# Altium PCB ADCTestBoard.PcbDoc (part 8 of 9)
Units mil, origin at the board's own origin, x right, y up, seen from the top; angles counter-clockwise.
Board outline 11022.62 x 9187 mil, 8 copper layers (TopLayer, InternalPlane1, InternalPlane2, InternalPlane3, InternalPlane4, InternalPlane5, MidLayer1, BottomLayer), stack 103.8 mil thick; 1282 components, 637 nets, 4473 pads, 1306 vias.
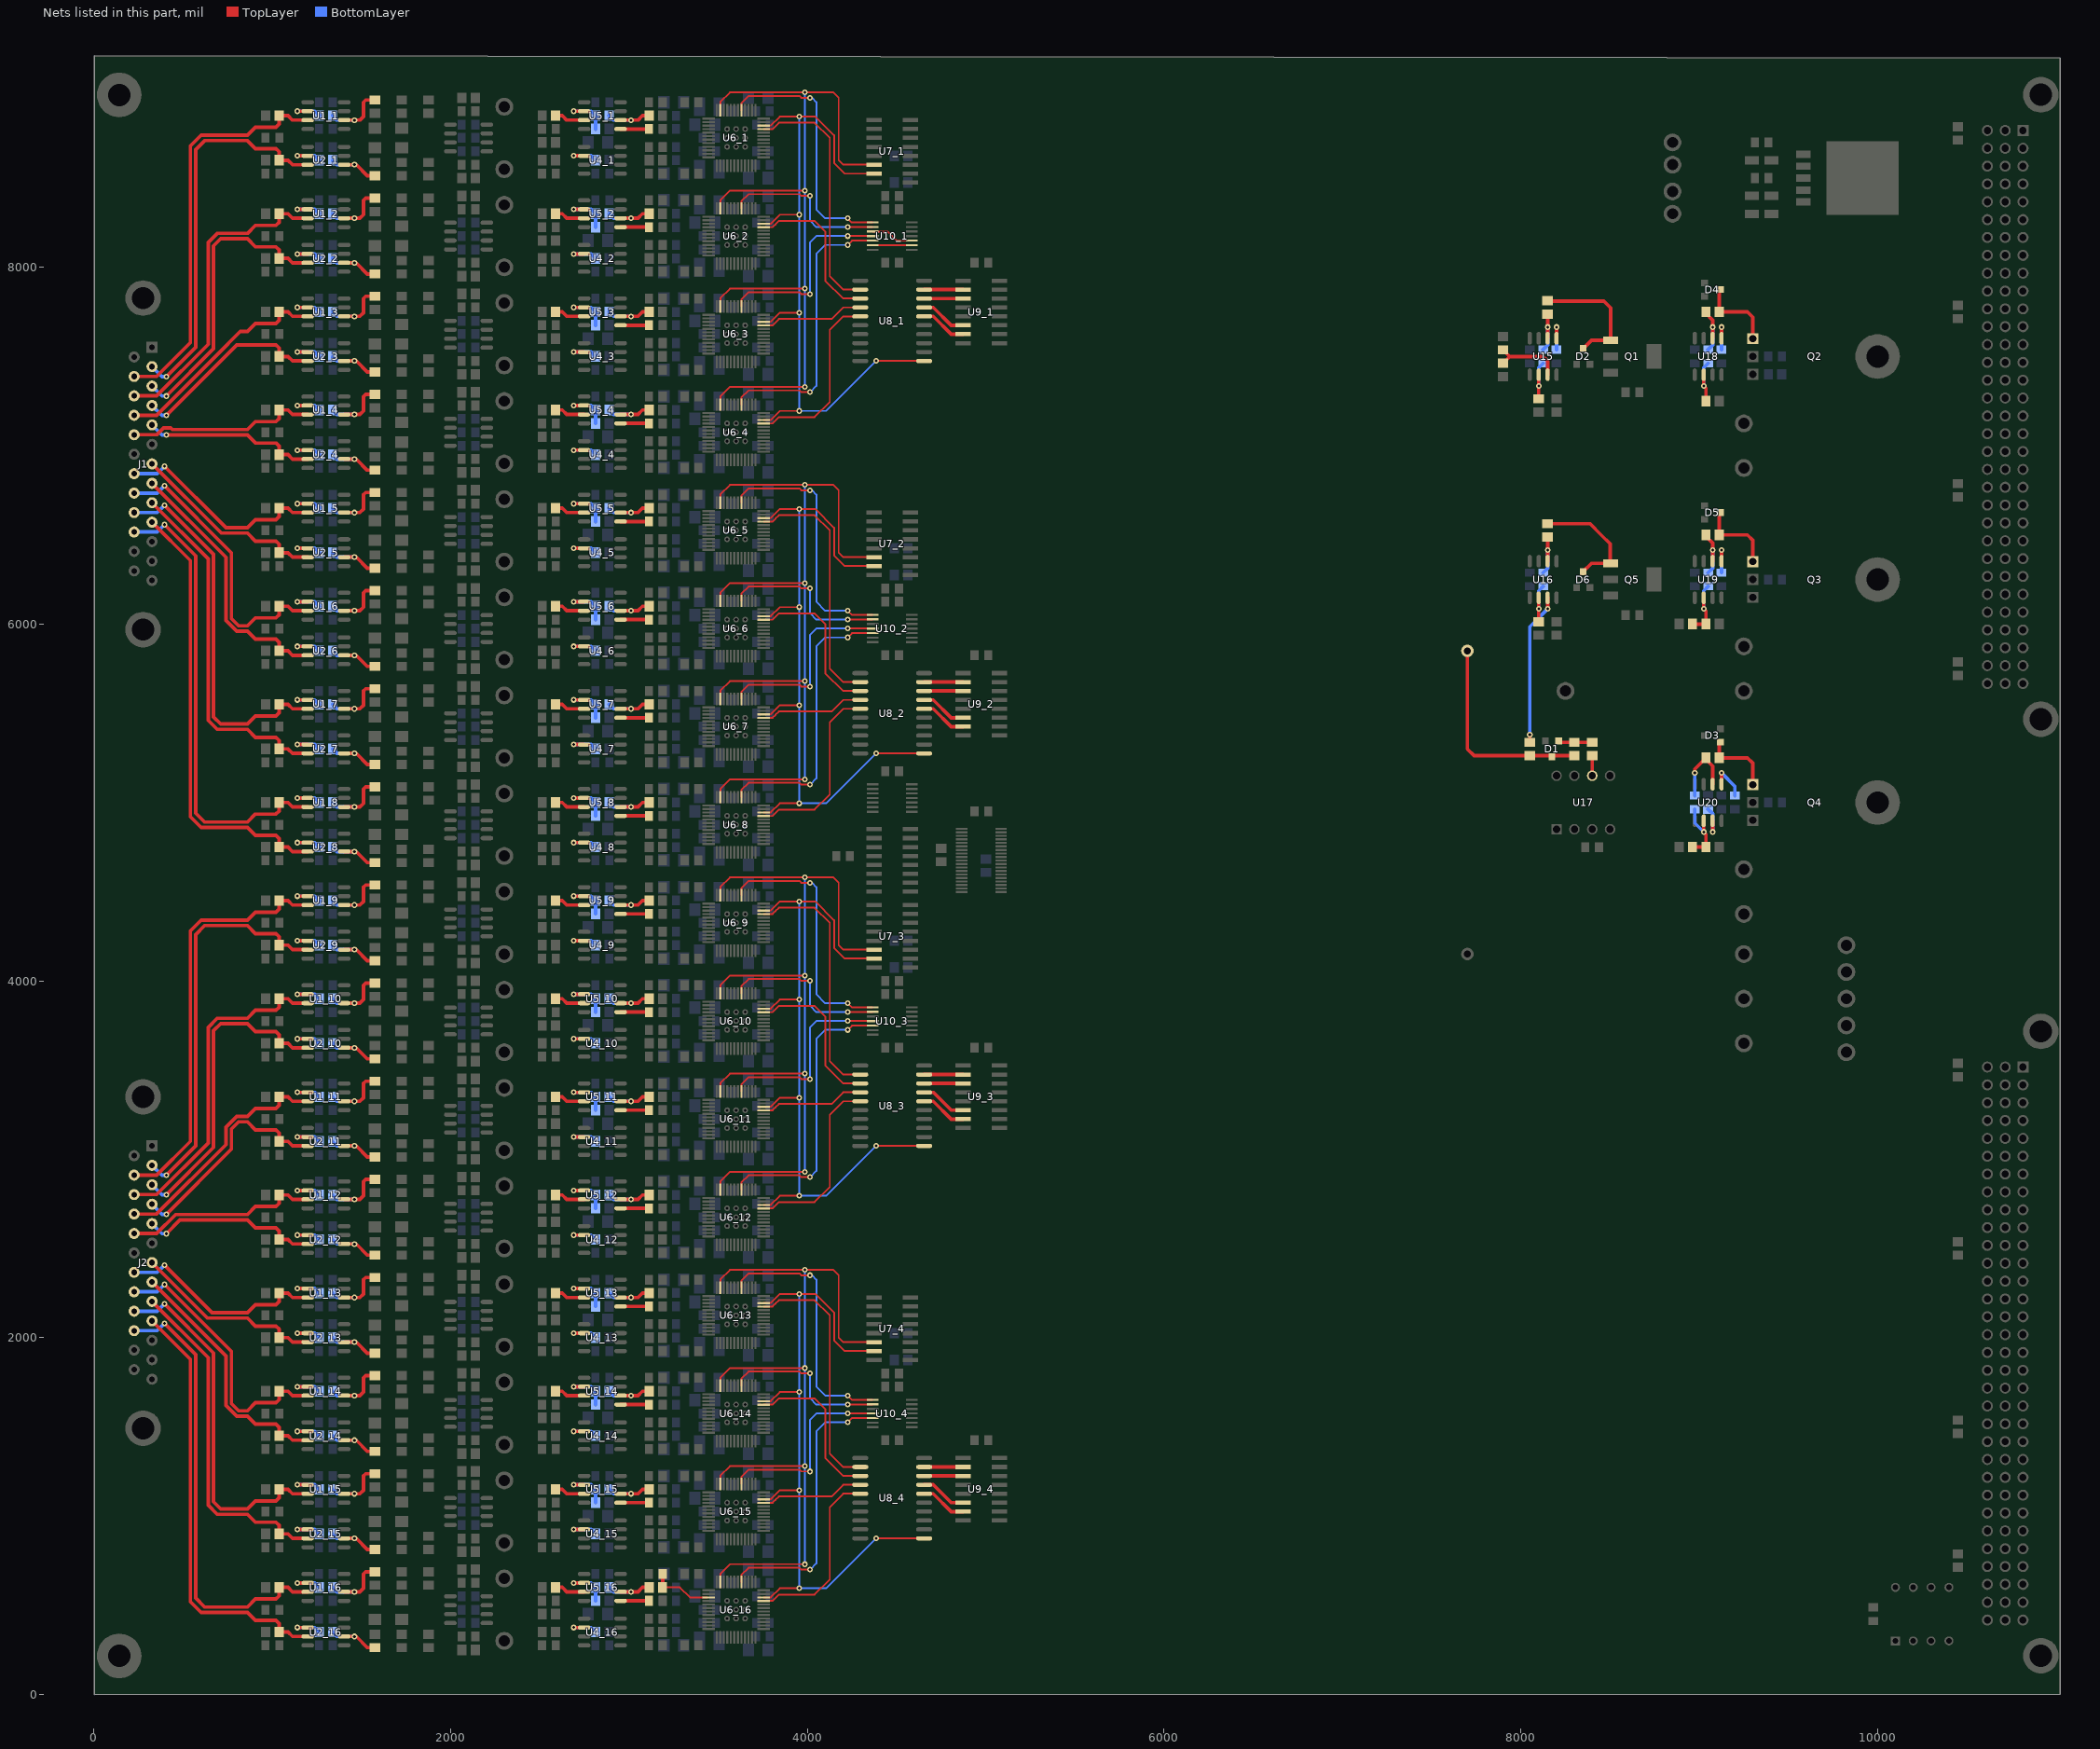
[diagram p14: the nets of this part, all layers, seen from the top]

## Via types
v1: diameter 32, hole 16, TopLayer to BottomLayer, 1306 vias

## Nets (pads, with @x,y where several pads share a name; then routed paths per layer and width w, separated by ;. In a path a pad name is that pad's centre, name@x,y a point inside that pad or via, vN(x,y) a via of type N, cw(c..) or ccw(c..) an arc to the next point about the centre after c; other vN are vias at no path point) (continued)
NetC36_16_1: C36_16.1 R19_16.1 U6_16.39 | length 346.9
  TopLayer w10: R19_16.1@3187.4,600 3285,600 3341.1,543.9 U6_16.39@3435.63,543.9
  TopLayer w20: R19_16.1@3187.4,600 3188.39,600.98 C36_16.1@3188.39,675
NetC37_1_1: C37_1.1 U5_1.5 | length 159.3
  TopLayer w20: U5_1.5@2952.36,8775 C37_1.1@3111.61,8775
NetC37_2_1: C37_2.1 U5_2.5 | length 159.3
  TopLayer w20: U5_2.5@2952.36,8225 C37_2.1@3111.61,8225
NetC37_3_1: C37_3.1 U5_3.5 | length 159.3
  TopLayer w20: U5_3.5@2952.36,7675 C37_3.1@3111.61,7675
NetC37_4_1: C37_4.1 U5_4.5 | length 159.3
  TopLayer w20: U5_4.5@2952.36,7125 C37_4.1@3111.61,7125
NetC37_5_1: C37_5.1 U5_5.5 | length 159.3
  TopLayer w20: U5_5.5@2952.36,6575 C37_5.1@3111.61,6575
NetC37_6_1: C37_6.1 U5_6.5 | length 159.3
  TopLayer w20: U5_6.5@2952.36,6025 C37_6.1@3111.61,6025
NetC37_7_1: C37_7.1 U5_7.5 | length 159.3
  TopLayer w20: U5_7.5@2952.36,5475 C37_7.1@3111.61,5475
NetC37_8_1: C37_8.1 U5_8.5 | length 159.3
  TopLayer w20: U5_8.5@2952.36,4925 C37_8.1@3111.61,4925
NetC37_9_1: C37_9.1 U5_9.5 | length 159.3
  TopLayer w20: U5_9.5@2952.36,4375 C37_9.1@3111.61,4375
NetC37_10_1: C37_10.1 U5_10.5 | length 159.3
  TopLayer w20: U5_10.5@2952.36,3825 C37_10.1@3111.61,3825
NetC37_11_1: C37_11.1 U5_11.5 | length 159.3
  TopLayer w20: U5_11.5@2952.36,3275 C37_11.1@3111.61,3275
NetC37_12_1: C37_12.1 U5_12.5 | length 159.3
  TopLayer w20: U5_12.5@2952.36,2725 C37_12.1@3111.61,2725
NetC37_13_1: C37_13.1 U5_13.5 | length 159.3
  TopLayer w20: U5_13.5@2952.36,2175 C37_13.1@3111.61,2175
NetC37_14_1: C37_14.1 U5_14.5 | length 159.3
  TopLayer w20: U5_14.5@2952.36,1625 C37_14.1@3111.61,1625
NetC37_15_1: C37_15.1 U5_15.5 | length 159.3
  TopLayer w20: U5_15.5@2952.36,1075 C37_15.1@3111.61,1075
NetC37_16_1: C37_16.1 U5_16.5 | length 159.3
  TopLayer w20: U5_16.5@2952.36,525 C37_16.1@3111.61,525
NetC48_1: C48.1 U15.5 | length 189.3
  TopLayer w20: U15.5@8200,7602.36 v1(8200,7665)
  BottomLayer w20: C48.1@8200,7538.39 v1(8200,7665)
NetC51_1: C51.1 R34.2 U15.2 | length 272.2
  TopLayer w20: R34.2@8100,7262.4 U15.2@8100,7397.64
  BottomLayer w20: v1(8100,7335) 8100,7436.61 C51.1@8125,7461.61
NetC51_2: C51.2 R29.2 U15.6 | length 272.2
  TopLayer w20: U15.6@8150,7602.36 R29.2@8150,7737.6
  BottomLayer w20: C51.2@8125,7538.39 8150,7563.39 v1(8150,7665)
NetC53_1: C53.1 D1.3 R31.2 R33.1 | length 1165.5
  TopLayer w20: C53.1@7700,5850 7700,5300 7737.4,5262.6 R31.2@8300,5262.6
NetC56_1: C56.1 U18.5 | length 189.3
  TopLayer w20: U18.5@9125,7602.36 v1(9125,7665)
  BottomLayer w20: C56.1@9125,7538.39 v1(9125,7665)
NetC57_1: C57.1 U19.5 | length 189.3
  TopLayer w20: U19.5@9125,6352.36 v1(9125,6415)
  BottomLayer w20: C57.1@9125,6288.39 v1(9125,6415)
NetC58_1: C58.1 R40.1 U20.6 | length 391.5
  TopLayer w20: v1(8975,5165) 8975,5187.4 R40.1@9037.6,5250 ; R40.1@9037.6,5240.87 9075,5203.47 U20.6@9075,5102.36
  BottomLayer w20: C58.1@8975,5038.39 v1(8975,5165)
NetC58_2: C58.2 R35.1 R36.1 U20.2 | length 393.2
  TopLayer w20: R36.1@8962.4,4750 R35.1@9037.6,4750 ; R35.1@9025,4762.6 R35.1@9037.6,4750 ; U20.2@9025,4897.64 v1(9025,4835) 9037.6,4822.4 R35.1@9037.6,4750
  BottomLayer w20: C58.2@8975,4961.61 8975,4885 v1(9025,4835)
NetC61_1: C61.1 R43.2 U18.2 | length 307.6
  TopLayer w20: R43.2@9025,7262.6 R43.2@9037.6,7250 9037.6,7322.4 v1(9025,7335) U18.2@9025,7397.64
  BottomLayer w20: v1(9025,7335) 9025,7436.61 C61.1@9050,7461.61
NetC61_2: C61.2 R37.2 U18.6 | length 291
  TopLayer w20: R37.2@9037.6,7740.87 9075,7703.47 U18.6@9075,7602.36
  BottomLayer w20: C61.2@9050,7538.39 9075,7563.39 v1(9075,7665)
NetC62_1: C62.1 R42.2 R44.1 U19.2 | length 382.8
  TopLayer w20: R42.2@8962.4,6000 R44.1@9037.6,6000 ; R44.1@9025,6012.6 R44.1@9037.6,6000 ; U19.2@9025,6147.64 v1(9025,6085) 9037.6,6072.4 R44.1@9037.6,6000
  BottomLayer w20: v1(9025,6085) 9025,6186.61 C62.1@9050,6211.61
NetC62_2: C62.2 R38.1 U19.6 | length 291
  TopLayer w20: R38.1@9037.6,6490.87 9075,6453.47 U19.6@9075,6352.36
  BottomLayer w20: C62.2@9050,6288.39 9075,6313.39 v1(9075,6415)
NetC63_2: C63.2 U20.5 | length 220.3
  TopLayer w20: U20.5@9125,5102.36 v1(9125,5165)
  BottomLayer w20: v1(9125,5165) 9200,5090 C63.2@9200,5038.39
NetC81_1: C81.1 R48.1 U16.2 | length 272.2
  TopLayer w20: R48.1@8100,6012.4 U16.2@8100,6147.64
  BottomLayer w20: v1(8100,6085) 8100,6186.61 C81.1@8125,6211.61
NetC81_2: C81.2 R26.1 U16.6 | length 272.2
  TopLayer w20: U16.6@8150,6352.36 R26.1@8150,6487.6
  BottomLayer w20: C81.2@8125,6288.39 8150,6313.39 v1(8150,6415)
NetD1_1: D1.1 R31.1 R32.2 | length 190.5
  TopLayer w20: D1.1@8212.4,5344.29 8219.29,5337.4 R32.2@8400,5337.4
NetD2_3: D2.3 Q1.1 R29.1 | length 726.2
  TopLayer w20: R29.1@8150,7809.45 8465.55,7809.45 8502.95,7772.05 Q1.1@8502.95,7590.55 ; D2.3@8350,7544.29 8396.26,7590.55 Q1.1@8502.95,7590.55 ; Q1.1@8500,7593.5 Q1.1@8502.95,7590.55
NetD3_1: D3.1 Q4.1 R40.2 | length 410.5
  TopLayer w20: D3.1@9119.29,5337.6 9112.4,5330.71 R40.2@9112.4,5250 9270,5250 9300,5220 Q4.1@9300,5100
NetD4_3: D4.3 Q2.1 R37.1 | length 447.9
  TopLayer w20: D4.3@9119.29,7875 9112.4,7868.11 R37.1@9112.4,7750 9270,7750 9300,7720 Q2.1@9300,7600
NetD5_3: D5.3 Q3.1 R38.2 | length 447.9
  TopLayer w20: D5.3@9119.29,6625 9112.4,6618.11 R38.2@9112.4,6500 9270,6500 9300,6470 Q3.1@9300,6350
NetD6_3: D6.3 Q5.1 R26.2 | length 679.3
  TopLayer w20: R26.2@8150,6562.4 8387.6,6562.4 8450,6500 8500,6450 8500,6343.5 Q5.1@8502.95,6340.55 8396.26,6340.55 D6.3@8350,6294.29
NetJ1_2: J1.2 R11_1.1 U2_1.3 | length 2176.5
  TopLayer w20: v1(404.92,7387.2) 570,7552.28 570,8660 620,8710 860,8710 905,8665 1020,8665 1037.4,8647.6 R11_1.1@1037.4,8600 1087.4,8600 1112.4,8575 U2_1.3@1197.64,8575
  BottomLayer w20: J1.2@324.92,7443.2 380.92,7387.2 v1(404.92,7387.2)
NetJ1_3: J1.3 R11_2.1 U2_2.3 | length 1682.8
  TopLayer w20: v1(404.92,7278.2) 670,7543.28 670,8120 710,8160 860,8160 905,8115 1020,8115 1037.4,8097.6 R11_2.1@1037.4,8050 1087.4,8050 1112.4,8025 U2_2.3@1197.64,8025
  BottomLayer w20: J1.3@324.92,7334.2 380.92,7278.2 v1(404.92,7278.2)
NetJ1_4: J1.4 R11_3.1 U2_3.3 | length 1125
  TopLayer w20: v1(404.92,7169.2) 800.72,7565 1020,7565 1037.4,7547.6 R11_3.1@1037.4,7500 1087.4,7500 1112.4,7475 U2_3.3@1197.64,7475
  BottomLayer w20: J1.4@324.92,7225.2 380.92,7169.2 v1(404.92,7169.2)
NetJ1_5: J1.5 R11_4.1 U2_4.3 | length 979.8
  TopLayer w20: v1(404.92,7060.2) 631.8,7060.2 632,7060 860,7060 905,7015 1020,7015 1037.4,6997.6 R11_4.1@1037.4,6950 1087.4,6950 1112.4,6925 U2_4.3@1197.64,6925
  BottomLayer w20: J1.5@324.92,7116.2 380.92,7060.2 v1(404.92,7060.2)
NetJ1_7: J1.7 R11_5.1 U2_5.3 | length 1117.3
  TopLayer w20: J1.7@324.92,6898.2 713.13,6510 860,6510 905,6465 1020,6465 1037.4,6447.6 R11_5.1@1037.4,6400 1087.4,6400 1112.4,6375 U2_5.3@1197.64,6375
NetJ1_8: J1.8 R11_6.1 U2_6.3 | length 1507.4
  TopLayer w20: J1.8@324.92,6789.2 740,6374.13 740,6020 800,5960 860,5960 905,5915 1020,5915 1037.4,5897.6 R11_6.1@1037.4,5850 1087.4,5850 1112.4,5825 U2_6.3@1197.64,5825
NetJ1_9: J1.9 R11_7.1 U2_7.3 | length 2012.9
  TopLayer w20: J1.9@324.92,6680.2 640,6365.13 640,5460 690,5410 860,5410 905,5365 1020,5365 1037.4,5347.6 R11_7.1@1037.4,5300 1087.4,5300 1112.4,5275 U2_7.3@1197.64,5275
NetJ1_10: J1.10 R11_8.1 U2_8.3 | length 2506.6
  TopLayer w20: J1.10@324.92,6571.2 540,6356.13 540,4920 600,4860 860,4860 905,4815 1020,4815 1037.4,4797.6 R11_8.1@1037.4,4750 1087.4,4750 1112.4,4725 U2_8.3@1197.64,4725
NetJ1_15: J1.15 R3_1.1 U1_1.3 | length 2262.4
  TopLayer w20: J1.15@224.92,7388.2 350.92,7388.2 540,7577.28 540,8680 600,8740 860,8740 905,8785 1020,8785 1037.4,8802.4 R3_1.1@1037.4,8850 1087.4,8850 1112.4,8825 U1_1.3@1197.64,8825
NetJ1_16: J1.16 R3_2.1 U1_2.3 | length 1768.7
  TopLayer w20: J1.16@224.92,7279.2 350.92,7279.2 640,7568.28 640,8140 690,8190 860,8190 905,8235 1020,8235 1037.4,8252.4 R3_2.1@1037.4,8300 1087.4,8300 1112.4,8275 U1_2.3@1197.64,8275
NetJ1_17: J1.17 R3_3.1 U1_3.3 | length 1251.3
  TopLayer w20: J1.17@224.92,7170.2 350.92,7170.2 690.36,7509.64 ; 690,7510 820,7640 860,7640 905,7685 1020,7685 1037.4,7702.4 R3_3.1@1037.4,7750 1087.4,7750 1112.4,7725 U1_3.3@1197.64,7725
NetJ1_18: J1.18 R3_4.1 U1_4.3 | length 1076.6
  TopLayer w20: J1.18@224.92,7061.2 350.92,7061.2 389.86,7100.14 ; 390,7100 430,7100 440,7090 860,7090 905,7135 1020,7135 1037.4,7152.4 R3_4.1@1037.4,7200 1087.4,7200 1112.4,7175 U1_4.3@1197.64,7175
NetJ1_20: J1.20 R3_5.1 U1_5.3 | length 1216.1
  TopLayer w20: v1(394.92,6884.2) 739.13,6540 860,6540 905,6585 1020,6585 1037.4,6602.4 R3_5.1@1037.4,6650 1087.4,6650 1112.4,6625 U1_5.3@1197.64,6625
  BottomLayer w20: J1.20@224.92,6843.2 353.92,6843.2 v1(394.92,6884.2)
NetJ1_21: J1.21 R3_6.1 U1_6.3 | length 1615.6
  TopLayer w20: v1(394.92,6775.2) 770,6400.13 770,6030 810,5990 860,5990 905,6035 1020,6035 1037.4,6052.4 R3_6.1@1037.4,6100 1087.4,6100 1112.4,6075 U1_6.3@1197.64,6075
  BottomLayer w20: J1.21@224.92,6734.2 353.92,6734.2 v1(394.92,6775.2)
NetJ1_22: J1.22 R3_7.1 U1_7.3 | length 2115.1
  TopLayer w20: v1(394.92,6666.2) 670,6391.13 670,5480 710,5440 860,5440 905,5485 1020,5485 1037.4,5502.4 R3_7.1@1037.4,5550 1087.4,5550 1112.4,5525 U1_7.3@1197.64,5525
  BottomLayer w20: J1.22@224.92,6625.2 353.92,6625.2 v1(394.92,6666.2)
NetJ1_23: J1.23 R3_8.1 U1_8.3 | length 2608.9
  TopLayer w20: v1(394.92,6557.2) 570,6382.13 570,4940 620,4890 860,4890 905,4935 1020,4935 1037.4,4952.4 R3_8.1@1037.4,5000 1087.4,5000 1112.4,4975 U1_8.3@1197.64,4975
  BottomLayer w20: J1.23@224.92,6516.2 353.92,6516.2 v1(394.92,6557.2)
NetJ2_2: J2.2 R11_9.1 U2_9.3 | length 2253.7
  TopLayer w20: v1(405,2910) 570,3075 570,4260 620,4310 860,4310 905,4265 1020,4265 1037.4,4247.6 R11_9.1@1037.4,4200 1087.4,4200 1112.4,4175 U2_9.3@1197.64,4175
  BottomLayer w20: J2.2@325,2966 381,2910 v1(405,2910)
NetJ2_3: J2.3 R11_10.1 U2_10.3 | length 1760
  TopLayer w20: v1(405,2801) 670,3066 670,3720 710,3760 860,3760 905,3715 1020,3715 1037.4,3697.6 R11_10.1@1037.4,3650 1087.4,3650 1112.4,3625 U2_10.3@1197.64,3625
  BottomLayer w20: J2.3@325,2857 381,2801 v1(405,2801)
NetJ2_4: J2.4 R11_11.1 U2_11.3 | length 1260.4
  TopLayer w20: v1(405,2692) 770,3057 770,3170 810,3210 860,3210 905,3165 1020,3165 1037.4,3147.6 R11_11.1@1037.4,3100 1087.4,3100 1112.4,3075 U2_11.3@1197.64,3075
  BottomLayer w20: J2.4@325,2748 381,2692 v1(405,2692)
NetJ2_5: J2.5 R11_12.1 U2_12.3 | length 1011.5
  TopLayer w20: v1(405,2583) 482,2660 860,2660 905,2615 1020,2615 1037.4,2597.6 R11_12.1@1037.4,2550 1087.4,2550 1112.4,2525 U2_12.3@1197.64,2525
  BottomLayer w20: J2.5@325,2639 381,2583 v1(405,2583)
NetJ2_7: J2.7 R11_13.1 U2_13.3 | length 1085.3
  TopLayer w20: J2.7@325,2421 636,2110 860,2110 905,2065 1020,2065 1037.4,2047.6 R11_13.1@1037.4,2000 1087.4,2000 1112.4,1975 U2_13.3@1197.64,1975
NetJ2_8: J2.8 R11_14.1 U2_14.3 | length 1430.2
  TopLayer w20: J2.8@325,2312 740,1897 740,1620 800,1560 860,1560 905,1515 1020,1515 1037.4,1497.6 R11_14.1@1037.4,1450 1087.4,1450 1112.4,1425 U2_14.3@1197.64,1425
NetJ2_9: J2.9 R11_15.1 U2_15.3 | length 1935.6
  TopLayer w20: J2.9@325,2203 640,1888 640,1060 690,1010 860,1010 905,965 1020,965 1037.4,947.6 R11_15.1@1037.4,900 1087.4,900 1112.4,875 U2_15.3@1197.64,875
NetJ2_10: J2.10 R11_16.1 U2_16.3 | length 2429.3
  TopLayer w20: J2.10@325,2094 540,1879 540,520 600,460 860,460 905,415 1020,415 1037.4,397.6 R11_16.1@1037.4,350 1087.4,350 1112.4,325 U2_16.3@1197.64,325
NetJ2_15: J2.15 R3_9.1 U1_9.3 | length 2339.6
  TopLayer w20: J2.15@225,2911 351,2911 540,3100 540,4280 600,4340 860,4340 905,4385 1020,4385 1037.4,4402.4 R3_9.1@1037.4,4450 1087.4,4450 1112.4,4425 U1_9.3@1197.64,4425
NetJ2_16: J2.16 R3_10.1 U1_10.3 | length 1845.9
  TopLayer w20: J2.16@225,2802 351,2802 640,3091 640,3740 690,3790 860,3790 905,3835 1020,3835 1037.4,3852.4 R3_10.1@1037.4,3900 1087.4,3900 1112.4,3875 U1_10.3@1197.64,3875
NetJ2_17: J2.17 R3_11.1 U1_11.3 | length 1340.4
  TopLayer w20: J2.17@225,2693 351,2693 740,3082 740,3180 800,3240 860,3240 905,3285 1020,3285 1037.4,3302.4 R3_11.1@1037.4,3350 1087.4,3350 1112.4,3325 U1_11.3@1197.64,3325
NetJ2_18: J2.18 R3_12.1 U1_12.3 | length 1100.3
  TopLayer w20: J2.18@225,2584 351,2584 457,2690 860,2690 905,2735 1020,2735 1037.4,2752.4 R3_12.1@1037.4,2800 1087.4,2800 1112.4,2775 U1_12.3@1197.64,2775
NetJ2_20: J2.20 R3_13.1 U1_13.3 | length 1184
  TopLayer w20: v1(395,2407) 662,2140 860,2140 905,2185 1020,2185 1037.4,2202.4 R3_13.1@1037.4,2250 1087.4,2250 1112.4,2225 U1_13.3@1197.64,2225
  BottomLayer w20: J2.20@225,2366 354,2366 v1(395,2407)
NetJ2_21: J2.21 R3_14.1 U1_14.3 | length 1538.3
  TopLayer w20: v1(395,2298) 770,1923 770,1630 810,1590 860,1590 905,1635 1020,1635 1037.4,1652.4 R3_14.1@1037.4,1700 1087.4,1700 1112.4,1675 U1_14.3@1197.64,1675
  BottomLayer w20: J2.21@225,2257 354,2257 v1(395,2298)
NetJ2_22: J2.22 R3_15.1 U1_15.3 | length 2037.9
  TopLayer w20: v1(395,2189) 670,1914 670,1080 710,1040 860,1040 905,1085 1020,1085 1037.4,1102.4 R3_15.1@1037.4,1150 1087.4,1150 1112.4,1125 U1_15.3@1197.64,1125
  BottomLayer w20: J2.22@225,2148 354,2148 v1(395,2189)
NetJ2_23: J2.23 R3_16.1 U1_16.3 | length 2531.6
  TopLayer w20: v1(395,2080) 570,1905 570,540 620,490 860,490 905,535 1020,535 1037.4,552.4 R3_16.1@1037.4,600 1087.4,600 1112.4,575 U1_16.3@1197.64,575
  BottomLayer w20: J2.23@225,2039 354,2039 v1(395,2080)
NetR1_1_1: R1_1.1 U1_1.2 | length 190.6
  TopLayer w20: v1(1140,8875) U1_1.2@1197.64,8875
  BottomLayer w20: v1(1140,8875) 1237.6,8875 R1_1.1@1262.6,8850
NetR1_1_2: R1_1.2 R4_1.1 U1_1.6 | length 399
  TopLayer w20: U1_1.6@1402.36,8825 1490,8825 1510,8845 1510,8925 1522.4,8937.4 R4_1.1@1575,8937.4
  BottomLayer w20: R1_1.2@1337.4,8850 1362.4,8825 v1(1460,8825)
NetR1_2_1: R1_2.1 U1_2.2 | length 190.6
  TopLayer w20: v1(1140,8325) U1_2.2@1197.64,8325
  BottomLayer w20: v1(1140,8325) 1237.6,8325 R1_2.1@1262.6,8300
NetR1_2_2: R1_2.2 R4_2.1 U1_2.6 | length 399
  TopLayer w20: U1_2.6@1402.36,8275 1490,8275 1510,8295 1510,8375 1522.4,8387.4 R4_2.1@1575,8387.4
  BottomLayer w20: R1_2.2@1337.4,8300 1362.4,8275 v1(1460,8275)
NetR1_3_1: R1_3.1 U1_3.2 | length 190.6
  TopLayer w20: v1(1140,7775) U1_3.2@1197.64,7775
  BottomLayer w20: v1(1140,7775) 1237.6,7775 R1_3.1@1262.6,7750
NetR1_3_2: R1_3.2 R4_3.1 U1_3.6 | length 399
  TopLayer w20: U1_3.6@1402.36,7725 1490,7725 1510,7745 1510,7825 1522.4,7837.4 R4_3.1@1575,7837.4
  BottomLayer w20: R1_3.2@1337.4,7750 1362.4,7725 v1(1460,7725)
NetR1_4_1: R1_4.1 U1_4.2 | length 190.6
  TopLayer w20: v1(1140,7225) U1_4.2@1197.64,7225
  BottomLayer w20: v1(1140,7225) 1237.6,7225 R1_4.1@1262.6,7200
NetR1_4_2: R1_4.2 R4_4.1 U1_4.6 | length 399
  TopLayer w20: U1_4.6@1402.36,7175 1490,7175 1510,7195 1510,7275 1522.4,7287.4 R4_4.1@1575,7287.4
  BottomLayer w20: R1_4.2@1337.4,7200 1362.4,7175 v1(1460,7175)
NetR1_5_1: R1_5.1 U1_5.2 | length 190.6
  TopLayer w20: v1(1140,6675) U1_5.2@1197.64,6675
  BottomLayer w20: v1(1140,6675) 1237.6,6675 R1_5.1@1262.6,6650
NetR1_5_2: R1_5.2 R4_5.1 U1_5.6 | length 399
  TopLayer w20: U1_5.6@1402.36,6625 1490,6625 1510,6645 1510,6725 1522.4,6737.4 R4_5.1@1575,6737.4
  BottomLayer w20: R1_5.2@1337.4,6650 1362.4,6625 v1(1460,6625)
NetR1_6_1: R1_6.1 U1_6.2 | length 190.6
  TopLayer w20: v1(1140,6125) U1_6.2@1197.64,6125
  BottomLayer w20: v1(1140,6125) 1237.6,6125 R1_6.1@1262.6,6100
NetR1_6_2: R1_6.2 R4_6.1 U1_6.6 | length 399
  TopLayer w20: U1_6.6@1402.36,6075 1490,6075 1510,6095 1510,6175 1522.4,6187.4 R4_6.1@1575,6187.4
  BottomLayer w20: R1_6.2@1337.4,6100 1362.4,6075 v1(1460,6075)
NetR1_7_1: R1_7.1 U1_7.2 | length 190.6
  TopLayer w20: v1(1140,5575) U1_7.2@1197.64,5575
  BottomLayer w20: v1(1140,5575) 1237.6,5575 R1_7.1@1262.6,5550
NetR1_7_2: R1_7.2 R4_7.1 U1_7.6 | length 399
  TopLayer w20: U1_7.6@1402.36,5525 1490,5525 1510,5545 1510,5625 1522.4,5637.4 R4_7.1@1575,5637.4
  BottomLayer w20: R1_7.2@1337.4,5550 1362.4,5525 v1(1460,5525)
NetR1_8_1: R1_8.1 U1_8.2 | length 190.6
  TopLayer w20: v1(1140,5025) U1_8.2@1197.64,5025
  BottomLayer w20: v1(1140,5025) 1237.6,5025 R1_8.1@1262.6,5000
NetR1_8_2: R1_8.2 R4_8.1 U1_8.6 | length 399
  TopLayer w20: U1_8.6@1402.36,4975 1490,4975 1510,4995 1510,5075 1522.4,5087.4 R4_8.1@1575,5087.4
  BottomLayer w20: R1_8.2@1337.4,5000 1362.4,4975 v1(1460,4975)
NetR1_9_1: R1_9.1 U1_9.2 | length 190.6
  TopLayer w20: v1(1140,4475) U1_9.2@1197.64,4475
  BottomLayer w20: v1(1140,4475) 1237.6,4475 R1_9.1@1262.6,4450
NetR1_9_2: R1_9.2 R4_9.1 U1_9.6 | length 399
  TopLayer w20: U1_9.6@1402.36,4425 1490,4425 1510,4445 1510,4525 1522.4,4537.4 R4_9.1@1575,4537.4
  BottomLayer w20: R1_9.2@1337.4,4450 1362.4,4425 v1(1460,4425)
NetR1_10_1: R1_10.1 U1_10.2 | length 190.6
  TopLayer w20: v1(1140,3925) U1_10.2@1197.64,3925
  BottomLayer w20: v1(1140,3925) 1237.6,3925 R1_10.1@1262.6,3900
NetR1_10_2: R1_10.2 R4_10.1 U1_10.6 | length 399
  TopLayer w20: U1_10.6@1402.36,3875 1490,3875 1510,3895 1510,3975 1522.4,3987.4 R4_10.1@1575,3987.4
  BottomLayer w20: R1_10.2@1337.4,3900 1362.4,3875 v1(1460,3875)
NetR1_11_1: R1_11.1 U1_11.2 | length 190.6
  TopLayer w20: v1(1140,3375) U1_11.2@1197.64,3375
  BottomLayer w20: v1(1140,3375) 1237.6,3375 R1_11.1@1262.6,3350
NetR1_11_2: R1_11.2 R4_11.1 U1_11.6 | length 399
  TopLayer w20: U1_11.6@1402.36,3325 1490,3325 1510,3345 1510,3425 1522.4,3437.4 R4_11.1@1575,3437.4
  BottomLayer w20: R1_11.2@1337.4,3350 1362.4,3325 v1(1460,3325)
NetR1_12_1: R1_12.1 U1_12.2 | length 190.6
  TopLayer w20: v1(1140,2825) U1_12.2@1197.64,2825
  BottomLayer w20: v1(1140,2825) 1237.6,2825 R1_12.1@1262.6,2800
NetR1_12_2: R1_12.2 R4_12.1 U1_12.6 | length 399
  TopLayer w20: U1_12.6@1402.36,2775 1490,2775 1510,2795 1510,2875 1522.4,2887.4 R4_12.1@1575,2887.4
  BottomLayer w20: R1_12.2@1337.4,2800 1362.4,2775 v1(1460,2775)
NetR1_13_1: R1_13.1 U1_13.2 | length 190.6
  TopLayer w20: v1(1140,2275) U1_13.2@1197.64,2275
  BottomLayer w20: v1(1140,2275) 1237.6,2275 R1_13.1@1262.6,2250
NetR1_13_2: R1_13.2 R4_13.1 U1_13.6 | length 399
  TopLayer w20: U1_13.6@1402.36,2225 1490,2225 1510,2245 1510,2325 1522.4,2337.4 R4_13.1@1575,2337.4
  BottomLayer w20: R1_13.2@1337.4,2250 1362.4,2225 v1(1460,2225)
NetR1_14_1: R1_14.1 U1_14.2 | length 190.6
  TopLayer w20: v1(1140,1725) U1_14.2@1197.64,1725
  BottomLayer w20: v1(1140,1725) 1237.6,1725 R1_14.1@1262.6,1700
NetR1_14_2: R1_14.2 R4_14.1 U1_14.6 | length 399
  TopLayer w20: U1_14.6@1402.36,1675 1490,1675 1510,1695 1510,1775 1522.4,1787.4 R4_14.1@1575,1787.4
  BottomLayer w20: R1_14.2@1337.4,1700 1362.4,1675 v1(1460,1675)
NetR1_15_1: R1_15.1 U1_15.2 | length 190.6
  TopLayer w20: v1(1140,1175) U1_15.2@1197.64,1175
  BottomLayer w20: v1(1140,1175) 1237.6,1175 R1_15.1@1262.6,1150
NetR1_15_2: R1_15.2 R4_15.1 U1_15.6 | length 399
  TopLayer w20: U1_15.6@1402.36,1125 1490,1125 1510,1145 1510,1225 1522.4,1237.4 R4_15.1@1575,1237.4
  BottomLayer w20: R1_15.2@1337.4,1150 1362.4,1125 v1(1460,1125)
NetR1_16_1: R1_16.1 U1_16.2 | length 190.6
  TopLayer w20: v1(1140,625) U1_16.2@1197.64,625
  BottomLayer w20: v1(1140,625) 1237.6,625 R1_16.1@1262.6,600
NetR1_16_2: R1_16.2 R4_16.1 U1_16.6 | length 399
  TopLayer w20: U1_16.6@1402.36,575 1490,575 1510,595 1510,675 1522.4,687.4 R4_16.1@1575,687.4
  BottomLayer w20: R1_16.2@1337.4,600 1362.4,575 v1(1460,575)
NetR9_1_1: R9_1.1 R13_1.2 U2_1.6 | length 331.4
  TopLayer w20: U2_1.6@1402.36,8575 1470,8575 1532.4,8512.6 R9_1.1@1575,8512.6
  BottomLayer w20: R13_1.2@1337.4,8600 1362.4,8575 v1(1460,8575)
NetR9_2_1: R9_2.1 R13_2.2 U2_2.6 | length 331.4
  TopLayer w20: U2_2.6@1402.36,8025 1470,8025 1532.4,7962.6 R9_2.1@1575,7962.6
  BottomLayer w20: R13_2.2@1337.4,8050 1362.4,8025 v1(1460,8025)
NetR9_3_1: R9_3.1 R13_3.2 U2_3.6 | length 331.4
  TopLayer w20: U2_3.6@1402.36,7475 1470,7475 1532.4,7412.6 R9_3.1@1575,7412.6
  BottomLayer w20: R13_3.2@1337.4,7500 1362.4,7475 v1(1460,7475)
NetR9_4_1: R9_4.1 R13_4.2 U2_4.6 | length 331.4
  TopLayer w20: U2_4.6@1402.36,6925 1470,6925 1532.4,6862.6 R9_4.1@1575,6862.6
  BottomLayer w20: R13_4.2@1337.4,6950 1362.4,6925 v1(1460,6925)
NetR9_5_1: R9_5.1 R13_5.2 U2_5.6 | length 331.4
  TopLayer w20: U2_5.6@1402.36,6375 1470,6375 1532.4,6312.6 R9_5.1@1575,6312.6
  BottomLayer w20: R13_5.2@1337.4,6400 1362.4,6375 v1(1460,6375)
NetR9_6_1: R9_6.1 R13_6.2 U2_6.6 | length 331.4
  TopLayer w20: U2_6.6@1402.36,5825 1470,5825 1532.4,5762.6 R9_6.1@1575,5762.6
  BottomLayer w20: R13_6.2@1337.4,5850 1362.4,5825 v1(1460,5825)
NetR9_7_1: R9_7.1 R13_7.2 U2_7.6 | length 331.4
  TopLayer w20: U2_7.6@1402.36,5275 1470,5275 1532.4,5212.6 R9_7.1@1575,5212.6
  BottomLayer w20: R13_7.2@1337.4,5300 1362.4,5275 v1(1460,5275)
NetR9_8_1: R9_8.1 R13_8.2 U2_8.6 | length 331.4
  TopLayer w20: U2_8.6@1402.36,4725 1470,4725 1532.4,4662.6 R9_8.1@1575,4662.6
  BottomLayer w20: R13_8.2@1337.4,4750 1362.4,4725 v1(1460,4725)
NetR9_9_1: R9_9.1 R13_9.2 U2_9.6 | length 331.4
  TopLayer w20: U2_9.6@1402.36,4175 1470,4175 1532.4,4112.6 R9_9.1@1575,4112.6
  BottomLayer w20: R13_9.2@1337.4,4200 1362.4,4175 v1(1460,4175)
NetR9_10_1: R9_10.1 R13_10.2 U2_10.6 | length 331.4
  TopLayer w20: U2_10.6@1402.36,3625 1470,3625 1532.4,3562.6 R9_10.1@1575,3562.6
  BottomLayer w20: R13_10.2@1337.4,3650 1362.4,3625 v1(1460,3625)
NetR9_11_1: R9_11.1 R13_11.2 U2_11.6 | length 331.4
  TopLayer w20: U2_11.6@1402.36,3075 1470,3075 1532.4,3012.6 R9_11.1@1575,3012.6
  BottomLayer w20: R13_11.2@1337.4,3100 1362.4,3075 v1(1460,3075)
NetR9_12_1: R9_12.1 R13_12.2 U2_12.6 | length 331.4
  TopLayer w20: U2_12.6@1402.36,2525 1470,2525 1532.4,2462.6 R9_12.1@1575,2462.6
  BottomLayer w20: R13_12.2@1337.4,2550 1362.4,2525 v1(1460,2525)
NetR9_13_1: R9_13.1 R13_13.2 U2_13.6 | length 331.4
  TopLayer w20: U2_13.6@1402.36,1975 1470,1975 1532.4,1912.6 R9_13.1@1575,1912.6
  BottomLayer w20: R13_13.2@1337.4,2000 1362.4,1975 v1(1460,1975)
NetR9_14_1: R9_14.1 R13_14.2 U2_14.6 | length 331.4
  TopLayer w20: U2_14.6@1402.36,1425 1470,1425 1532.4,1362.6 R9_14.1@1575,1362.6
  BottomLayer w20: R13_14.2@1337.4,1450 1362.4,1425 v1(1460,1425)
NetR9_15_1: R9_15.1 R13_15.2 U2_15.6 | length 331.4
  TopLayer w20: U2_15.6@1402.36,875 1470,875 1532.4,812.6 R9_15.1@1575,812.6
  BottomLayer w20: R13_15.2@1337.4,900 1362.4,875 v1(1460,875)
NetR9_16_1: R9_16.1 R13_16.2 U2_16.6 | length 331.4
  TopLayer w20: U2_16.6@1402.36,325 1470,325 1532.4,262.6 R9_16.1@1575,262.6
  BottomLayer w20: R13_16.2@1337.4,350 1362.4,325 v1(1460,325)
NetR13_1_1: R13_1.1 U2_1.2 | length 190.6
  TopLayer w20: v1(1140,8625) U2_1.2@1197.64,8625
  BottomLayer w20: v1(1140,8625) 1237.6,8625 R13_1.1@1262.6,8600
NetR13_2_1: R13_2.1 U2_2.2 | length 190.6
  TopLayer w20: v1(1140,8075) U2_2.2@1197.64,8075
  BottomLayer w20: v1(1140,8075) 1237.6,8075 R13_2.1@1262.6,8050
NetR13_3_1: R13_3.1 U2_3.2 | length 190.6
  TopLayer w20: v1(1140,7525) U2_3.2@1197.64,7525
  BottomLayer w20: v1(1140,7525) 1237.6,7525 R13_3.1@1262.6,7500
NetR13_4_1: R13_4.1 U2_4.2 | length 190.6
  TopLayer w20: v1(1140,6975) U2_4.2@1197.64,6975
  BottomLayer w20: v1(1140,6975) 1237.6,6975 R13_4.1@1262.6,6950
NetR13_5_1: R13_5.1 U2_5.2 | length 190.6
  TopLayer w20: v1(1140,6425) U2_5.2@1197.64,6425
  BottomLayer w20: v1(1140,6425) 1237.6,6425 R13_5.1@1262.6,6400
NetR13_6_1: R13_6.1 U2_6.2 | length 190.6
  TopLayer w20: v1(1140,5875) U2_6.2@1197.64,5875
  BottomLayer w20: v1(1140,5875) 1237.6,5875 R13_6.1@1262.6,5850
NetR13_7_1: R13_7.1 U2_7.2 | length 190.6
  TopLayer w20: v1(1140,5325) U2_7.2@1197.64,5325
  BottomLayer w20: v1(1140,5325) 1237.6,5325 R13_7.1@1262.6,5300
NetR13_8_1: R13_8.1 U2_8.2 | length 190.6
  TopLayer w20: v1(1140,4775) U2_8.2@1197.64,4775
  BottomLayer w20: v1(1140,4775) 1237.6,4775 R13_8.1@1262.6,4750
NetR13_9_1: R13_9.1 U2_9.2 | length 190.6
  TopLayer w20: v1(1140,4225) U2_9.2@1197.64,4225
  BottomLayer w20: v1(1140,4225) 1237.6,4225 R13_9.1@1262.6,4200
NetR13_10_1: R13_10.1 U2_10.2 | length 190.6
  TopLayer w20: v1(1140,3675) U2_10.2@1197.64,3675
  BottomLayer w20: v1(1140,3675) 1237.6,3675 R13_10.1@1262.6,3650
NetR13_11_1: R13_11.1 U2_11.2 | length 190.6
  TopLayer w20: v1(1140,3125) U2_11.2@1197.64,3125
  BottomLayer w20: v1(1140,3125) 1237.6,3125 R13_11.1@1262.6,3100
NetR13_12_1: R13_12.1 U2_12.2 | length 190.6
  TopLayer w20: v1(1140,2575) U2_12.2@1197.64,2575
  BottomLayer w20: v1(1140,2575) 1237.6,2575 R13_12.1@1262.6,2550
NetR13_13_1: R13_13.1 U2_13.2 | length 190.6
  TopLayer w20: v1(1140,2025) U2_13.2@1197.64,2025
  BottomLayer w20: v1(1140,2025) 1237.6,2025 R13_13.1@1262.6,2000
NetR13_14_1: R13_14.1 U2_14.2 | length 190.6
  TopLayer w20: v1(1140,1475) U2_14.2@1197.64,1475
  BottomLayer w20: v1(1140,1475) 1237.6,1475 R13_14.1@1262.6,1450
NetR13_15_1: R13_15.1 U2_15.2 | length 190.6
  TopLayer w20: v1(1140,925) U2_15.2@1197.64,925
  BottomLayer w20: v1(1140,925) 1237.6,925 R13_15.1@1262.6,900
NetR13_16_1: R13_16.1 U2_16.2 | length 190.6
  TopLayer w20: v1(1140,375) U2_16.2@1197.64,375
  BottomLayer w20: v1(1140,375) 1237.6,375 R13_16.1@1262.6,350
NetR15_1_1: R15_1.1 R19_1.2 U5_1.6 | length 303.5
  TopLayer w20: U5_1.6@2952.36,8825 3050,8825 3075,8850 R19_1.2@3112.6,8850
  BottomLayer w20: R15_1.1@2887.4,8850 2912.4,8825 v1(3010,8825)
NetR15_1_2: R15_1.2 R16_1.1 U5_1.2 | length 265.6
  TopLayer w20: v1(2690,8875) U5_1.2@2747.64,8875
  BottomLayer w20: v1(2690,8875) 2787.6,8875 R15_1.2@2812.6,8850 R16_1.1@2812.6,8775
NetR15_2_1: R15_2.1 R19_2.2 U5_2.6 | length 303.5
  TopLayer w20: U5_2.6@2952.36,8275 3050,8275 3075,8300 R19_2.2@3112.6,8300
  BottomLayer w20: R15_2.1@2887.4,8300 2912.4,8275 v1(3010,8275)
NetR15_2_2: R15_2.2 R16_2.1 U5_2.2 | length 265.6
  TopLayer w20: v1(2690,8325) U5_2.2@2747.64,8325
  BottomLayer w20: v1(2690,8325) 2787.6,8325 R15_2.2@2812.6,8300 R16_2.1@2812.6,8225
NetR15_3_1: R15_3.1 R19_3.2 U5_3.6 | length 303.5
  TopLayer w20: U5_3.6@2952.36,7725 3050,7725 3075,7750 R19_3.2@3112.6,7750
  BottomLayer w20: R15_3.1@2887.4,7750 2912.4,7725 v1(3010,7725)
NetR15_3_2: R15_3.2 R16_3.1 U5_3.2 | length 265.6
  TopLayer w20: v1(2690,7775) U5_3.2@2747.64,7775
  BottomLayer w20: v1(2690,7775) 2787.6,7775 R15_3.2@2812.6,7750 R16_3.1@2812.6,7675
NetR15_4_1: R15_4.1 R19_4.2 U5_4.6 | length 303.5
  TopLayer w20: U5_4.6@2952.36,7175 3050,7175 3075,7200 R19_4.2@3112.6,7200
  BottomLayer w20: R15_4.1@2887.4,7200 2912.4,7175 v1(3010,7175)
NetR15_4_2: R15_4.2 R16_4.1 U5_4.2 | length 265.6
  TopLayer w20: v1(2690,7225) U5_4.2@2747.64,7225
  BottomLayer w20: v1(2690,7225) 2787.6,7225 R15_4.2@2812.6,7200 R16_4.1@2812.6,7125
NetR15_5_1: R15_5.1 R19_5.2 U5_5.6 | length 303.5
  TopLayer w20: U5_5.6@2952.36,6625 3050,6625 3075,6650 R19_5.2@3112.6,6650
  BottomLayer w20: R15_5.1@2887.4,6650 2912.4,6625 v1(3010,6625)
NetR15_5_2: R15_5.2 R16_5.1 U5_5.2 | length 265.6
  TopLayer w20: v1(2690,6675) U5_5.2@2747.64,6675
  BottomLayer w20: v1(2690,6675) 2787.6,6675 R15_5.2@2812.6,6650 R16_5.1@2812.6,6575
NetR15_6_1: R15_6.1 R19_6.2 U5_6.6 | length 303.5
  TopLayer w20: U5_6.6@2952.36,6075 3050,6075 3075,6100 R19_6.2@3112.6,6100
  BottomLayer w20: R15_6.1@2887.4,6100 2912.4,6075 v1(3010,6075)
NetR15_6_2: R15_6.2 R16_6.1 U5_6.2 | length 265.6
  TopLayer w20: v1(2690,6125) U5_6.2@2747.64,6125
  BottomLayer w20: v1(2690,6125) 2787.6,6125 R15_6.2@2812.6,6100 R16_6.1@2812.6,6025
NetR15_7_1: R15_7.1 R19_7.2 U5_7.6 | length 303.5
  TopLayer w20: U5_7.6@2952.36,5525 3050,5525 3075,5550 R19_7.2@3112.6,5550
  BottomLayer w20: R15_7.1@2887.4,5550 2912.4,5525 v1(3010,5525)
NetR15_7_2: R15_7.2 R16_7.1 U5_7.2 | length 265.6
  TopLayer w20: v1(2690,5575) U5_7.2@2747.64,5575
  BottomLayer w20: v1(2690,5575) 2787.6,5575 R15_7.2@2812.6,5550 R16_7.1@2812.6,5475
NetR15_8_1: R15_8.1 R19_8.2 U5_8.6 | length 303.5
  TopLayer w20: U5_8.6@2952.36,4975 3050,4975 3075,5000 R19_8.2@3112.6,5000
  BottomLayer w20: R15_8.1@2887.4,5000 2912.4,4975 v1(3010,4975)
NetR15_8_2: R15_8.2 R16_8.1 U5_8.2 | length 265.6
  TopLayer w20: v1(2690,5025) U5_8.2@2747.64,5025
  BottomLayer w20: v1(2690,5025) 2787.6,5025 R15_8.2@2812.6,5000 R16_8.1@2812.6,4925
NetR15_9_1: R15_9.1 R19_9.2 U5_9.6 | length 303.5
  TopLayer w20: U5_9.6@2952.36,4425 3050,4425 3075,4450 R19_9.2@3112.6,4450
  BottomLayer w20: R15_9.1@2887.4,4450 2912.4,4425 v1(3010,4425)
NetR15_9_2: R15_9.2 R16_9.1 U5_9.2 | length 265.6
  TopLayer w20: v1(2690,4475) U5_9.2@2747.64,4475
  BottomLayer w20: v1(2690,4475) 2787.6,4475 R15_9.2@2812.6,4450 R16_9.1@2812.6,4375
NetR15_10_1: R15_10.1 R19_10.2 U5_10.6 | length 303.5
  TopLayer w20: U5_10.6@2952.36,3875 3050,3875 3075,3900 R19_10.2@3112.6,3900
  BottomLayer w20: R15_10.1@2887.4,3900 2912.4,3875 v1(3010,3875)
NetR15_10_2: R15_10.2 R16_10.1 U5_10.2 | length 265.6
  TopLayer w20: v1(2690,3925) U5_10.2@2747.64,3925
  BottomLayer w20: v1(2690,3925) 2787.6,3925 R15_10.2@2812.6,3900 R16_10.1@2812.6,3825
NetR15_11_1: R15_11.1 R19_11.2 U5_11.6 | length 303.5
  TopLayer w20: U5_11.6@2952.36,3325 3050,3325 3075,3350 R19_11.2@3112.6,3350
  BottomLayer w20: R15_11.1@2887.4,3350 2912.4,3325 v1(3010,3325)
NetR15_11_2: R15_11.2 R16_11.1 U5_11.2 | length 265.6
  TopLayer w20: v1(2690,3375) U5_11.2@2747.64,3375
  BottomLayer w20: v1(2690,3375) 2787.6,3375 R15_11.2@2812.6,3350 R16_11.1@2812.6,3275
NetR15_12_1: R15_12.1 R19_12.2 U5_12.6 | length 303.5
  TopLayer w20: U5_12.6@2952.36,2775 3050,2775 3075,2800 R19_12.2@3112.6,2800
  BottomLayer w20: R15_12.1@2887.4,2800 2912.4,2775 v1(3010,2775)
NetR15_12_2: R15_12.2 R16_12.1 U5_12.2 | length 265.6
  TopLayer w20: v1(2690,2825) U5_12.2@2747.64,2825
  BottomLayer w20: v1(2690,2825) 2787.6,2825 R15_12.2@2812.6,2800 R16_12.1@2812.6,2725
NetR15_13_1: R15_13.1 R19_13.2 U5_13.6 | length 303.5
  TopLayer w20: U5_13.6@2952.36,2225 3050,2225 3075,2250 R19_13.2@3112.6,2250
  BottomLayer w20: R15_13.1@2887.4,2250 2912.4,2225 v1(3010,2225)
NetR15_13_2: R15_13.2 R16_13.1 U5_13.2 | length 265.6
  TopLayer w20: v1(2690,2275) U5_13.2@2747.64,2275
  BottomLayer w20: v1(2690,2275) 2787.6,2275 R15_13.2@2812.6,2250 R16_13.1@2812.6,2175
NetR15_14_1: R15_14.1 R19_14.2 U5_14.6 | length 303.5
  TopLayer w20: U5_14.6@2952.36,1675 3050,1675 3075,1700 R19_14.2@3112.6,1700
  BottomLayer w20: R15_14.1@2887.4,1700 2912.4,1675 v1(3010,1675)
NetR15_14_2: R15_14.2 R16_14.1 U5_14.2 | length 265.6
  TopLayer w20: v1(2690,1725) U5_14.2@2747.64,1725
  BottomLayer w20: v1(2690,1725) 2787.6,1725 R15_14.2@2812.6,1700 R16_14.1@2812.6,1625
NetR15_15_1: R15_15.1 R19_15.2 U5_15.6 | length 303.5
  TopLayer w20: U5_15.6@2952.36,1125 3050,1125 3075,1150 R19_15.2@3112.6,1150
  BottomLayer w20: R15_15.1@2887.4,1150 2912.4,1125 v1(3010,1125)
NetR15_15_2: R15_15.2 R16_15.1 U5_15.2 | length 265.6
  TopLayer w20: v1(2690,1175) U5_15.2@2747.64,1175
  BottomLayer w20: v1(2690,1175) 2787.6,1175 R15_15.2@2812.6,1150 R16_15.1@2812.6,1075
NetR15_16_1: R15_16.1 R19_16.2 U5_16.6 | length 303.5
  TopLayer w20: U5_16.6@2952.36,575 3050,575 3075,600 R19_16.2@3112.6,600
  BottomLayer w20: R15_16.1@2887.4,600 2912.4,575 v1(3010,575)
NetR15_16_2: R15_16.2 R16_16.1 U5_16.2 | length 265.6
  TopLayer w20: v1(2690,625) U5_16.2@2747.64,625
  BottomLayer w20: v1(2690,625) 2787.6,625 R15_16.2@2812.6,600 R16_16.1@2812.6,525
NetR20_1_1: R20_1.1 U5_1.3 | length 170.6
  TopLayer w20: R20_1.1@2587.4,8850 2625,8850 2650,8825 U5_1.3@2747.64,8825
NetR20_2_1: R20_2.1 U5_2.3 | length 170.6
  TopLayer w20: R20_2.1@2587.4,8300 2625,8300 2650,8275 U5_2.3@2747.64,8275
NetR20_3_1: R20_3.1 U5_3.3 | length 170.6
  TopLayer w20: R20_3.1@2587.4,7750 2625,7750 2650,7725 U5_3.3@2747.64,7725
NetR20_4_1: R20_4.1 U5_4.3 | length 170.6
  TopLayer w20: R20_4.1@2587.4,7200 2625,7200 2650,7175 U5_4.3@2747.64,7175
NetR20_5_1: R20_5.1 U5_5.3 | length 170.6
  TopLayer w20: R20_5.1@2587.4,6650 2625,6650 2650,6625 U5_5.3@2747.64,6625
NetR20_6_1: R20_6.1 U5_6.3 | length 170.6
  TopLayer w20: R20_6.1@2587.4,6100 2625,6100 2650,6075 U5_6.3@2747.64,6075
NetR20_7_1: R20_7.1 U5_7.3 | length 170.6
  TopLayer w20: R20_7.1@2587.4,5550 2625,5550 2650,5525 U5_7.3@2747.64,5525
NetR20_8_1: R20_8.1 U5_8.3 | length 170.6
  TopLayer w20: R20_8.1@2587.4,5000 2625,5000 2650,4975 U5_8.3@2747.64,4975
NetR20_9_1: R20_9.1 U5_9.3 | length 170.6
  TopLayer w20: R20_9.1@2587.4,4450 2625,4450 2650,4425 U5_9.3@2747.64,4425
NetR20_10_1: R20_10.1 U5_10.3 | length 170.6
  TopLayer w20: R20_10.1@2587.4,3900 2625,3900 2650,3875 U5_10.3@2747.64,3875
NetR20_11_1: R20_11.1 U5_11.3 | length 170.6
  TopLayer w20: R20_11.1@2587.4,3350 2625,3350 2650,3325 U5_11.3@2747.64,3325
NetR20_12_1: R20_12.1 U5_12.3 | length 170.6
  TopLayer w20: R20_12.1@2587.4,2800 2625,2800 2650,2775 U5_12.3@2747.64,2775
NetR20_13_1: R20_13.1 U5_13.3 | length 170.6
  TopLayer w20: R20_13.1@2587.4,2250 2625,2250 2650,2225 U5_13.3@2747.64,2225
NetR20_14_1: R20_14.1 U5_14.3 | length 170.6
  TopLayer w20: R20_14.1@2587.4,1700 2625,1700 2650,1675 U5_14.3@2747.64,1675
NetR20_15_1: R20_15.1 U5_15.3 | length 170.6
  TopLayer w20: R20_15.1@2587.4,1150 2625,1150 2650,1125 U5_15.3@2747.64,1125
NetR20_16_1: R20_16.1 U5_16.3 | length 170.6
  TopLayer w20: R20_16.1@2587.4,600 2625,600 2650,575 U5_16.3@2747.64,575
NetR21_1_1: R21_1.1 U4_1.2 | length 190.6
  TopLayer w20: v1(2690,8625) U4_1.2@2747.64,8625
  BottomLayer w20: v1(2690,8625) 2787.6,8625 R21_1.1@2812.6,8600
NetR21_2_1: R21_2.1 U4_2.2 | length 190.6
  TopLayer w20: v1(2690,8075) U4_2.2@2747.64,8075
  BottomLayer w20: v1(2690,8075) 2787.6,8075 R21_2.1@2812.6,8050
NetR21_3_1: R21_3.1 U4_3.2 | length 190.6
  TopLayer w20: v1(2690,7525) U4_3.2@2747.64,7525
  BottomLayer w20: v1(2690,7525) 2787.6,7525 R21_3.1@2812.6,7500
NetR21_4_1: R21_4.1 U4_4.2 | length 190.6
  TopLayer w20: v1(2690,6975) U4_4.2@2747.64,6975
  BottomLayer w20: v1(2690,6975) 2787.6,6975 R21_4.1@2812.6,6950
NetR21_5_1: R21_5.1 U4_5.2 | length 190.6
  TopLayer w20: v1(2690,6425) U4_5.2@2747.64,6425
  BottomLayer w20: v1(2690,6425) 2787.6,6425 R21_5.1@2812.6,6400
NetR21_6_1: R21_6.1 U4_6.2 | length 190.6
  TopLayer w20: v1(2690,5875) U4_6.2@2747.64,5875
  BottomLayer w20: v1(2690,5875) 2787.6,5875 R21_6.1@2812.6,5850
NetR21_7_1: R21_7.1 U4_7.2 | length 190.6
  TopLayer w20: v1(2690,5325) U4_7.2@2747.64,5325
  BottomLayer w20: v1(2690,5325) 2787.6,5325 R21_7.1@2812.6,5300
NetR21_8_1: R21_8.1 U4_8.2 | length 190.6
  TopLayer w20: v1(2690,4775) U4_8.2@2747.64,4775
  BottomLayer w20: v1(2690,4775) 2787.6,4775 R21_8.1@2812.6,4750
NetR21_9_1: R21_9.1 U4_9.2 | length 190.6
  TopLayer w20: v1(2690,4225) U4_9.2@2747.64,4225
  BottomLayer w20: v1(2690,4225) 2787.6,4225 R21_9.1@2812.6,4200
NetR21_10_1: R21_10.1 U4_10.2 | length 190.6
  TopLayer w20: v1(2690,3675) U4_10.2@2747.64,3675
  BottomLayer w20: v1(2690,3675) 2787.6,3675 R21_10.1@2812.6,3650
NetR21_11_1: R21_11.1 U4_11.2 | length 190.6
  TopLayer w20: v1(2690,3125) U4_11.2@2747.64,3125
  BottomLayer w20: v1(2690,3125) 2787.6,3125 R21_11.1@2812.6,3100
NetR21_12_1: R21_12.1 U4_12.2 | length 190.6
  TopLayer w20: v1(2690,2575) U4_12.2@2747.64,2575
  BottomLayer w20: v1(2690,2575) 2787.6,2575 R21_12.1@2812.6,2550
NetR21_13_1: R21_13.1 U4_13.2 | length 190.6
  TopLayer w20: v1(2690,2025) U4_13.2@2747.64,2025
  BottomLayer w20: v1(2690,2025) 2787.6,2025 R21_13.1@2812.6,2000
NetR21_14_1: R21_14.1 U4_14.2 | length 190.6
  TopLayer w20: v1(2690,1475) U4_14.2@2747.64,1475
  BottomLayer w20: v1(2690,1475) 2787.6,1475 R21_14.1@2812.6,1450
NetR21_15_1: R21_15.1 U4_15.2 | length 190.6
  TopLayer w20: v1(2690,925) U4_15.2@2747.64,925
  BottomLayer w20: v1(2690,925) 2787.6,925 R21_15.1@2812.6,900
NetR21_16_1: R21_16.1 U4_16.2 | length 190.6
  TopLayer w20: v1(2690,375) U4_16.2@2747.64,375
  BottomLayer w20: v1(2690,375) 2787.6,375 R21_16.1@2812.6,350
NetR27_1: R27.1 R28.2 U15.3 | length 406.5
  TopLayer w20: R27.1@7900,7462.4 7937.6,7500 ; R28.2@7900,7537.6 7937.6,7500 ; U15.3@8150,7397.64 8150,7475 8125,7500 7937.6,7500
NetR32_1: R32.1 U17.6 | length 112.6
  TopLayer w20: U17.6@8400,5150 R32.1@8400,5262.6
NetR33_2: R33.2 U16.3 | length 851.7
  TopLayer w20: R33.2@8050,5337.4 v1(8050,5380) ; v1(8150,6085) U16.3@8150,6147.64
  BottomLayer w20: v1(8050,5380) 8050,5985 v1(8150,6085)
NetR41_2: R41.2 U20.3 | length 200.6
  TopLayer w20: v1(9075,4835) U20.3@9075,4897.64
  BottomLayer w20: R41.2@9050,4962.6 9075,4937.6 v1(9075,4835)
NetU6_1_21: U6_1.21 U8_1.2 | length 1397.1
  TopLayer w10: U6_1.21@3755,8774.21 3804.51,8774.21 3820.15,8789.85 ; 3820,8790 3840,8810 4040,8810 4125,8725 4125,7950 4200,7875 U8_1.2@4295.87,7875
NetU6_1_22: U6_1.22 U6_2.22 U6_3.22 U6_4.22 U7_1.15 U8_1.11 | length 3990.8
  TopLayer w10: U6_4.22@3755,7143.9 3793.9,7143.9 3845,7195 v1(3955,7195) ; U6_3.22@3755,7693.9 3793.9,7693.9 3845,7745 v1(3955,7745) ; U6_2.22@3755,8243.9 3793.9,8243.9 3845,8295 v1(3955,8295) ; U6_1.22@3755,8793.9 3793.9,8793.9 3845,8845 4045,8845 4150,8740 4150,8585 4210,8525 U7_1.15@4372.64,8525 ; v1(4385,7475) U8_1.11@4654.13,7475
  BottomLayer w10: v1(3955,8845) v1(3955,7195) 4105,7195 v1(4385,7475)
NetU6_1_29: U6_1.29 U10_1.1 | length 1427.3
  TopLayer w10: U6_1.29@3629.53,8880 3629.53,8919.53 3670,8960 3955,8960 3965,8950 v1(4015,8950) ; v1(4225,8275) 4248.23,8251.77 U10_1.1@4365.75,8251.77
  BottomLayer w10: v1@4025,8950 4050,8925 4050,8325 4100,8275 v1(4225,8275)
NetU6_1_35: U6_1.35 U6_2.35 U6_3.35 U6_4.35 U7_1.14 | length 4541.7
  TopLayer w10: U6_4.35@3511.42,7239.37 3511.42,7276.42 3565,7330 v1(3985,7330) ; U6_3.35@3511.42,7789.37 3511.42,7826.42 3565,7880 v1(3985,7880) ; U6_2.35@3511.42,8339.37 3511.42,8376.42 3565,8430 v1(3985,8430) ; U6_1.35@3511.42,8889.37 3511.42,8926.42 3565,8980 4145,8980 4175,8950 4175,8600 4200,8575 U7_1.14@4372.64,8575
  BottomLayer w10: v1(3985,7330) v1(3985,8980)
NetU6_2_21: U6_2.21 U8_1.3 | length 897.1
  TopLayer w10: U6_2.21@3755,8224.21 3804.51,8224.21 3820.15,8239.85 ; 3820,8240 3840,8260 4040,8260 4100,8200 4100,7925 4200,7825 U8_1.3@4295.87,7825
NetU6_2_29: U6_2.29 U10_1.2 | length 951.6
  TopLayer w10: U6_2.29@3629.53,8330 3629.53,8369.53 3670,8410 3955,8410 3965,8400 v1(4015,8400) ; v1(4225,8225) 4226.18,8226.18 U10_1.2@4365.75,8226.18
  BottomLayer w10: v1(4015,8400) 4015,8260 4050,8225 v1(4225,8225)
NetU6_3_21: U6_3.21 U8_1.4 | length 582.7
  TopLayer w10: U6_3.21@3755,7674.21 3804.51,7674.21 3820.15,7689.85 ; 3820,7690 3840,7710 4135,7710 4200,7775 U8_1.4@4295.87,7775
NetU6_3_29: U6_3.29 U10_1.4 | length 1101.2
  TopLayer w10: U6_3.29@3629.53,7780 3629.53,7819.53 3670,7860 3955,7860 3965,7850 v1(4015,7850) ; v1(4225,8175) U10_1.4@4365.75,8175
  BottomLayer w10: v1(4015,7850) 4015,8140 4050,8175 v1(4225,8175)
NetU6_4_21: U6_4.21 U8_1.5 | length 1027.1
  TopLayer w10: U6_4.21@3755,7124.21 3804.51,7124.21 3820.15,7139.85 ; 3820,7140 3840,7160 4040,7160 4125,7245 4125,7650 4200,7725 U8_1.5@4295.87,7725
NetU6_4_29: U6_4.29 U10_1.5 | length 1582
  TopLayer w10: U6_4.29@3629.53,7230 3629.53,7269.53 3670,7310 3955,7310 3965,7300 v1(4015,7300) ; v1(4225,8125) 4249.41,8149.41 U10_1.5@4365.75,8149.41
  BottomLayer w10: v1(4015,7300) 4050,7335 4050,8075 4100,8125 v1(4225,8125)
NetU6_5_21: U6_5.21 U8_2.2 | length 1397.1
  TopLayer w10: U6_5.21@3755,6574.21 3804.51,6574.21 3820.15,6589.85 ; 3820,6590 3840,6610 4040,6610 4125,6525 4125,5750 4200,5675 U8_2.2@4295.87,5675
NetU6_5_22: U6_5.22 U6_6.22 U6_7.22 U6_8.22 U7_2.15 U8_2.11 | length 3990.8
  TopLayer w10: U6_8.22@3755,4943.9 3793.9,4943.9 3845,4995 v1(3955,4995) ; U6_7.22@3755,5493.9 3793.9,5493.9 3845,5545 v1(3955,5545) ; U6_6.22@3755,6043.9 3793.9,6043.9 3845,6095 v1(3955,6095) ; U6_5.22@3755,6593.9 3793.9,6593.9 3845,6645 4045,6645 4150,6540 4150,6385 4210,6325 U7_2.15@4372.64,6325 ; v1(4385,5275) U8_2.11@4654.13,5275
  BottomLayer w10: v1(3955,6645) v1(3955,4995) 4105,4995 v1(4385,5275)
NetU6_5_29: U6_5.29 U10_2.1 | length 1427.3
  TopLayer w10: U6_5.29@3629.53,6680 3629.53,6719.53 3670,6760 3955,6760 3965,6750 v1(4015,6750) ; v1(4225,6075) 4248.23,6051.77 U10_2.1@4365.75,6051.77
  BottomLayer w10: v1@4025,6750 4050,6725 4050,6125 4100,6075 v1(4225,6075)
NetU6_5_35: U6_5.35 U6_6.35 U6_7.35 U6_8.35 U7_2.14 | length 4541.7
  TopLayer w10: U6_8.35@3511.42,5039.37 3511.42,5076.42 3565,5130 v1(3985,5130) ; U6_7.35@3511.42,5589.37 3511.42,5626.42 3565,5680 v1(3985,5680) ; U6_6.35@3511.42,6139.37 3511.42,6176.42 3565,6230 v1(3985,6230) ; U6_5.35@3511.42,6689.37 3511.42,6726.42 3565,6780 4145,6780 4175,6750 4175,6400 4200,6375 U7_2.14@4372.64,6375
  BottomLayer w10: v1(3985,5130) v1(3985,6780)
NetU6_6_21: U6_6.21 U8_2.3 | length 897.1
  TopLayer w10: U6_6.21@3755,6024.21 3804.51,6024.21 3820.15,6039.85 ; 3820,6040 3840,6060 4040,6060 4100,6000 4100,5725 4200,5625 U8_2.3@4295.87,5625
NetU6_6_29: U6_6.29 U10_2.2 | length 951.6
  TopLayer w10: U6_6.29@3629.53,6130 3629.53,6169.53 3670,6210 3955,6210 3965,6200 v1(4015,6200) ; v1(4225,6025) 4226.18,6026.18 U10_2.2@4365.75,6026.18
  BottomLayer w10: v1(4015,6200) 4015,6060 4050,6025 v1(4225,6025)
NetU6_7_21: U6_7.21 U8_2.4 | length 582.7
  TopLayer w10: U6_7.21@3755,5474.21 3804.51,5474.21 3820.15,5489.85 ; 3820,5490 3840,5510 4135,5510 4200,5575 U8_2.4@4295.87,5575
NetU6_7_29: U6_7.29 U10_2.4 | length 1101.2
  TopLayer w10: U6_7.29@3629.53,5580 3629.53,5619.53 3670,5660 3955,5660 3965,5650 v1(4015,5650) ; v1(4225,5975) U10_2.4@4365.75,5975
  BottomLayer w10: v1(4015,5650) 4015,5940 4050,5975 v1(4225,5975)
NetU6_8_21: U6_8.21 U8_2.5 | length 1027.1
  TopLayer w10: U6_8.21@3755,4924.21 3804.51,4924.21 3820.15,4939.85 ; 3820,4940 3840,4960 4040,4960 4125,5045 4125,5450 4200,5525 U8_2.5@4295.87,5525
NetU6_8_29: U6_8.29 U10_2.5 | length 1582
  TopLayer w10: U6_8.29@3629.53,5030 3629.53,5069.53 3670,5110 3955,5110 3965,5100 v1(4015,5100) ; v1(4225,5925) 4249.41,5949.41 U10_2.5@4365.75,5949.41
  BottomLayer w10: v1(4015,5100) 4050,5135 4050,5875 4100,5925 v1(4225,5925)
NetU6_9_21: U6_9.21 U8_3.2 | length 1397.1
  TopLayer w10: U6_9.21@3755,4374.21 3804.51,4374.21 3820.15,4389.85 ; 3820,4390 3840,4410 4040,4410 4125,4325 4125,3550 4200,3475 U8_3.2@4295.87,3475
NetU6_9_22: U6_9.22 U6_10.22 U6_11.22 U6_12.22 U7_3.15 U8_3.11 | length 3990.8
  TopLayer w10: U6_12.22@3755,2743.9 3793.9,2743.9 3845,2795 v1(3955,2795) ; U6_11.22@3755,3293.9 3793.9,3293.9 3845,3345 v1(3955,3345) ; U6_10.22@3755,3843.9 3793.9,3843.9 3845,3895 v1(3955,3895) ; U6_9.22@3755,4393.9 3793.9,4393.9 3845,4445 4045,4445 4150,4340 4150,4185 4210,4125 U7_3.15@4372.64,4125 ; v1(4385,3075) U8_3.11@4654.13,3075
  BottomLayer w10: v1(3955,4445) v1(3955,2795) 4105,2795 v1(4385,3075)
NetU6_9_29: U6_9.29 U10_3.1 | length 1427.3
  TopLayer w10: U6_9.29@3629.53,4480 3629.53,4519.53 3670,4560 3955,4560 3965,4550 v1(4015,4550) ; v1(4225,3875) 4248.23,3851.77 U10_3.1@4365.75,3851.77
  BottomLayer w10: v1@4025,4550 4050,4525 4050,3925 4100,3875 v1(4225,3875)
NetU6_9_35: U6_9.35 U6_10.35 U6_11.35 U6_12.35 U7_3.14 | length 4541.7
  TopLayer w10: U6_12.35@3511.42,2839.37 3511.42,2876.42 3565,2930 v1(3985,2930) ; U6_11.35@3511.42,3389.37 3511.42,3426.42 3565,3480 v1(3985,3480) ; U6_10.35@3511.42,3939.37 3511.42,3976.42 3565,4030 v1(3985,4030) ; U6_9.35@3511.42,4489.37 3511.42,4526.42 3565,4580 4145,4580 4175,4550 4175,4200 4200,4175 U7_3.14@4372.64,4175
  BottomLayer w10: v1(3985,2930) v1(3985,4580)
NetU6_10_21: U6_10.21 U8_3.3 | length 897.1
  TopLayer w10: U6_10.21@3755,3824.21 3804.51,3824.21 3820.15,3839.85 ; 3820,3840 3840,3860 4040,3860 4100,3800 4100,3525 4200,3425 U8_3.3@4295.87,3425
NetU6_10_29: U6_10.29 U10_3.2 | length 951.6
  TopLayer w10: U6_10.29@3629.53,3930 3629.53,3969.53 3670,4010 3955,4010 3965,4000 v1(4015,4000) ; v1(4225,3825) 4226.18,3826.18 U10_3.2@4365.75,3826.18
  BottomLayer w10: v1(4015,4000) 4015,3860 4050,3825 v1(4225,3825)
NetU6_11_21: U6_11.21 U8_3.4 | length 582.7
  TopLayer w10: U6_11.21@3755,3274.21 3804.51,3274.21 3820.15,3289.85 ; 3820,3290 3840,3310 4135,3310 4200,3375 U8_3.4@4295.87,3375
NetU6_11_29: U6_11.29 U10_3.4 | length 1101.2
  TopLayer w10: U6_11.29@3629.53,3380 3629.53,3419.53 3670,3460 3955,3460 3965,3450 v1(4015,3450) ; v1(4225,3775) U10_3.4@4365.75,3775
  BottomLayer w10: v1(4015,3450) 4015,3740 4050,3775 v1(4225,3775)
NetU6_12_21: U6_12.21 U8_3.5 | length 1027.1
  TopLayer w10: U6_12.21@3755,2724.21 3804.51,2724.21 3820.15,2739.85 ; 3820,2740 3840,2760 4040,2760 4125,2845 4125,3250 4200,3325 U8_3.5@4295.87,3325
NetU6_12_29: U6_12.29 U10_3.5 | length 1582
  TopLayer w10: U6_12.29@3629.53,2830 3629.53,2869.53 3670,2910 3955,2910 3965,2900 v1(4015,2900) ; v1(4225,3725) 4249.41,3749.41 U10_3.5@4365.75,3749.41
  BottomLayer w10: v1(4015,2900) 4050,2935 4050,3675 4100,3725 v1(4225,3725)
NetU6_13_21: U6_13.21 U8_4.2 | length 1397.1
  TopLayer w10: U6_13.21@3755,2174.21 3804.51,2174.21 3820.15,2189.85 ; 3820,2190 3840,2210 4040,2210 4125,2125 4125,1350 4200,1275 U8_4.2@4295.87,1275
NetU6_13_22: U6_13.22 U6_14.22 U6_15.22 U6_16.22 U7_4.15 U8_4.11 | length 3990.8
  TopLayer w10: U6_16.22@3755,543.9 3793.9,543.9 3845,595 v1(3955,595) ; U6_15.22@3755,1093.9 3793.9,1093.9 3845,1145 v1(3955,1145) ; U6_14.22@3755,1643.9 3793.9,1643.9 3845,1695 v1(3955,1695) ; U6_13.22@3755,2193.9 3793.9,2193.9 3845,2245 4045,2245 4150,2140 4150,1985 4210,1925 U7_4.15@4372.64,1925 ; v1(4385,875) U8_4.11@4654.13,875
  BottomLayer w10: v1(3955,2245) v1(3955,595) 4105,595 v1(4385,875)
NetU6_13_29: U6_13.29 U10_4.1 | length 1427.3
  TopLayer w10: U6_13.29@3629.53,2280 3629.53,2319.53 3670,2360 3955,2360 3965,2350 v1(4015,2350) ; v1(4225,1675) 4248.23,1651.77 U10_4.1@4365.75,1651.77
  BottomLayer w10: v1@4025,2350 4050,2325 4050,1725 4100,1675 v1(4225,1675)
NetU6_13_35: U6_13.35 U6_14.35 U6_15.35 U6_16.35 U7_4.14 | length 4541.7
  TopLayer w10: U6_16.35@3511.42,639.37 3511.42,676.42 3565,730 v1(3985,730) ; U6_15.35@3511.42,1189.37 3511.42,1226.42 3565,1280 v1(3985,1280) ; U6_14.35@3511.42,1739.37 3511.42,1776.42 3565,1830 v1(3985,1830) ; U6_13.35@3511.42,2289.37 3511.42,2326.42 3565,2380 4145,2380 4175,2350 4175,2000 4200,1975 U7_4.14@4372.64,1975
  BottomLayer w10: v1(3985,730) v1(3985,2380)
NetU6_14_21: U6_14.21 U8_4.3 | length 897.1
  TopLayer w10: U6_14.21@3755,1624.21 3804.51,1624.21 3820.15,1639.85 ; 3820,1640 3840,1660 4040,1660 4100,1600 4100,1325 4200,1225 U8_4.3@4295.87,1225
NetU6_14_29: U6_14.29 U10_4.2 | length 951.6
  TopLayer w10: U6_14.29@3629.53,1730 3629.53,1769.53 3670,1810 3955,1810 3965,1800 v1(4015,1800) ; v1(4225,1625) 4226.18,1626.18 U10_4.2@4365.75,1626.18
  BottomLayer w10: v1(4015,1800) 4015,1660 4050,1625 v1(4225,1625)
NetU6_15_21: U6_15.21 U8_4.4 | length 582.7
  TopLayer w10: U6_15.21@3755,1074.21 3804.51,1074.21 3820.15,1089.85 ; 3820,1090 3840,1110 4135,1110 4200,1175 U8_4.4@4295.87,1175
NetU6_15_29: U6_15.29 U10_4.4 | length 1101.2
  TopLayer w10: U6_15.29@3629.53,1180 3629.53,1219.53 3670,1260 3955,1260 3965,1250 v1(4015,1250) ; v1(4225,1575) U10_4.4@4365.75,1575
  BottomLayer w10: v1(4015,1250) 4015,1540 4050,1575 v1(4225,1575)
NetU6_16_21: U6_16.21 U8_4.5 | length 1027.1
  TopLayer w10: U6_16.21@3755,524.21 3804.51,524.21 3820.15,539.85 ; 3820,540 3840,560 4040,560 4125,645 4125,1050 4200,1125 U8_4.5@4295.87,1125
NetU6_16_29: U6_16.29 U10_4.5 | length 1582
  TopLayer w10: U6_16.29@3629.53,630 3629.53,669.53 3670,710 3955,710 3965,700 v1(4015,700) ; v1(4225,1525) 4249.41,1549.41 U10_4.5@4365.75,1549.41
  BottomLayer w10: v1(4015,700) 4050,735 4050,1475 4100,1525 v1(4225,1525)
NetU8_1_16: U8_1.16 U9_1.7 | length 259.9
  TopLayer w20: U8_1.16@4654.13,7725 4705,7725 4805,7625 U9_1.7@4872.64,7625
NetU8_1_17: U8_1.17 U9_1.6 | length 259.9
  TopLayer w20: U8_1.17@4654.13,7775 4705,7775 4805,7675 U9_1.6@4872.64,7675
NetU8_1_18: U8_1.18 U9_1.3 | length 218.5
  TopLayer w20: U8_1.18@4654.13,7825 U9_1.3@4872.64,7825
NetU8_1_19: U8_1.19 U9_1.2 | length 218.5
  TopLayer w20: U8_1.19@4654.13,7875 U9_1.2@4872.64,7875
NetU8_2_16: U8_2.16 U9_2.7 | length 259.9
  TopLayer w20: U8_2.16@4654.13,5525 4705,5525 4805,5425 U9_2.7@4872.64,5425
NetU8_2_17: U8_2.17 U9_2.6 | length 259.9
  TopLayer w20: U8_2.17@4654.13,5575 4705,5575 4805,5475 U9_2.6@4872.64,5475
NetU8_2_18: U8_2.18 U9_2.3 | length 218.5
  TopLayer w20: U8_2.18@4654.13,5625 U9_2.3@4872.64,5625
NetU8_2_19: U8_2.19 U9_2.2 | length 218.5
  TopLayer w20: U8_2.19@4654.13,5675 U9_2.2@4872.64,5675
NetU8_3_16: U8_3.16 U9_3.7 | length 259.9
  TopLayer w20: U8_3.16@4654.13,3325 4705,3325 4805,3225 U9_3.7@4872.64,3225
NetU8_3_17: U8_3.17 U9_3.6 | length 259.9
  TopLayer w20: U8_3.17@4654.13,3375 4705,3375 4805,3275 U9_3.6@4872.64,3275
NetU8_3_18: U8_3.18 U9_3.3 | length 218.5
  TopLayer w20: U8_3.18@4654.13,3425 U9_3.3@4872.64,3425
NetU8_3_19: U8_3.19 U9_3.2 | length 218.5
  TopLayer w20: U8_3.19@4654.13,3475 U9_3.2@4872.64,3475
NetU8_4_16: U8_4.16 U9_4.7 | length 259.9
  TopLayer w20: U8_4.16@4654.13,1125 4705,1125 4805,1025 U9_4.7@4872.64,1025
NetU8_4_17: U8_4.17 U9_4.6 | length 259.9
  TopLayer w20: U8_4.17@4654.13,1175 4705,1175 4805,1075 U9_4.6@4872.64,1075
NetU8_4_18: U8_4.18 U9_4.3 | length 218.5
  TopLayer w20: U8_4.18@4654.13,1225 U9_4.3@4872.64,1225
NetU8_4_19: U8_4.19 U9_4.2 | length 218.5
  TopLayer w20: U8_4.19@4654.13,1275 U9_4.2@4872.64,1275
NetU10_1_3: U10_1.3 U10_1.10 | length 239.7
  TopLayer w10: U10_1.3@4365.75,8200.59 4449.41,8200.59 4500.59,8149.41 U10_1.10@4584.25,8149.41
NetU10_1_6: U10_1.6 U10_1.9 | length 218.5
  TopLayer w10: U10_1.6@4365.75,8123.82 U10_1.9@4584.25,8123.82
